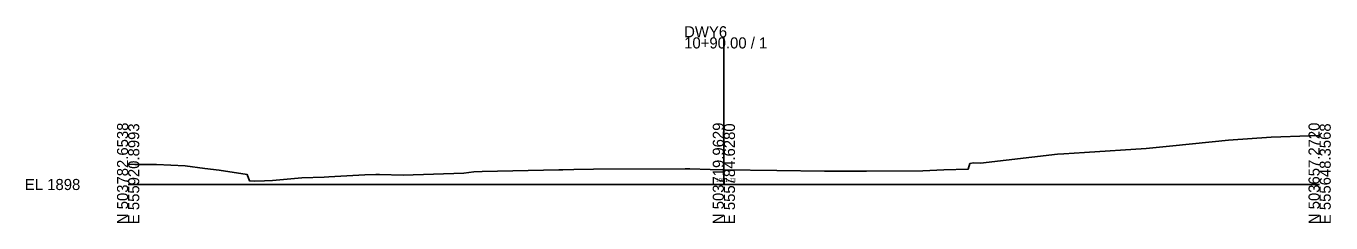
# Model space of a CAD drawing. Extents: x -26 to 1503, y -10 to 1030.
# Drawn here: x 1174.3 to 1502.8, y -9.7 to 39.9 of the extents above; entities that cross this region are included whole.
import ezdxf

# ---------------------------------------------------------------- set-up
doc = ezdxf.new("R2010")
doc.units = 0
for name, color, linetype in [('Exist Cross Section Cell', 7, 'Continuous'), ('Exist XS Ground Line', 7, 'Continuous'), ('Prop XS Ditch Standard Text', 7, 'Continuous')]:
    doc.layers.add(name, color=color, linetype=linetype)

msp = doc.modelspace()

# ---------------------------------------------------------------- linework, layer by layer
at = {"layer": 'Exist Cross Section Cell'}
for p, q in [((1350, 0), (1350, 37.1)), ((1200, 0), (1350, 0)), ((1350, 0), (1500, 0))]:
    msp.add_line(p, q, dxfattribs=at)
at = {"layer": 'Exist XS Ground Line'}
msp.add_lwpolyline([(1200, 5.14), (1201.65, 5.01), (1207.16, 5.01), (1214.38, 4.69), (1219.3, 4.06), (1222.96, 3.58), (1230.01, 2.48), (1230.58, 0.89), (1231.86, 0.88), (1234.36, 0.9), (1236.39, 1.01), (1243.71, 1.65), (1249.34, 1.88), (1250.52, 1.91), (1252.01, 2), (1259.6, 2.46), (1262.4, 2.52), (1263.26, 2.51), (1269.29, 2.37), (1284.56, 2.86), (1287.07, 3.17), (1289.15, 3.24), (1308.44, 3.7), (1309.47, 3.73), (1312.23, 3.8), (1317.2, 3.85), (1340.24, 3.96), (1341.41, 3.96), (1346.56, 3.78), (1350, 3.73), (1363.31, 3.51), (1375.34, 3.34), (1385.94, 3.37), (1400.08, 3.48), (1405.39, 3.66), (1411.52, 3.89), (1411.95, 5.27), (1412.84, 5.42), (1414.62, 5.37), (1433.99, 7.61), (1435.61, 7.76), (1440.8, 8.09), (1456.35, 9.09), (1463.04, 9.73), (1477.05, 11.21), (1487.82, 11.94), (1497.48, 12.3), (1500, 12.37)], dxfattribs=at)

# ---------------------------------------------------------------- texts
at = {"layer": 'Exist Cross Section Cell'}
for s, p in [('DWY6', (1340, 37.1)), ('10+90.00 / 1', (1340, 34.3)), ('EL 1898', (1174, -1.4))]:
    msp.add_text(s, height=2.8, dxfattribs=at).set_placement(p)
for s, p in [('N 503782.6538', (1200, -10)), ('E 555920.8993', (1202.8, -10)), ('N 503719.9629', (1350, -10)), ('E 555784.6280', (1352.8, -10)), ('N 503657.2720', (1500, -10)), ('E 555648.3568', (1502.8, -10))]:
    msp.add_text(s, height=2.8, rotation=90, dxfattribs=at).set_placement(p)
at = {"layer": 'Prop XS Ditch Standard Text'}
msp.add_text('1901.73', height=1, dxfattribs=at).set_placement((1347.99, 0.62))

doc.saveas('drawing.dxf')
